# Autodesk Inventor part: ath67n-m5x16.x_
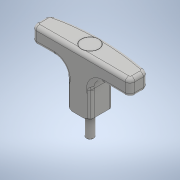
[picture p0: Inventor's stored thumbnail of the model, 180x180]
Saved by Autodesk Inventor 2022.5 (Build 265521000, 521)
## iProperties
Part Number: ath67n-m5x16.x_
Material: 一般
Document SubType Name: Modeling
Designer: ImaoCorp
Density: 1 g/cm^3
Appearance: 既定
Sending System: SOLIDWORKS 2017-2017317
MC: AMD64
MC_MODEL: Intel64 Family 6 Model 60 Stepping 3, GenuineIntel
OS: Windows_NT
FRU: Parasolid Version 29.0, build 201,  4-17-2017
FORMAT: text
GUISE: transmit
KEY: ath67n-m5x16
FILE: ath67n-m5x16.x_t
DATE: Tue Feb 05 16:18:05 2019
Author: ImaoCorp
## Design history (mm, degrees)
feature "Base1"
node "ソリッド1"
